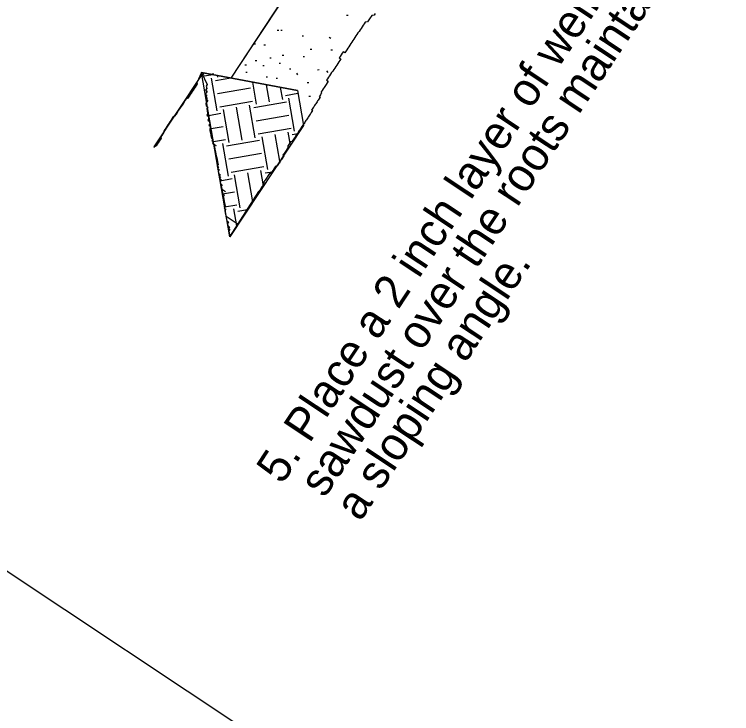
# Model space of a CAD drawing. Extents: x 561231 to 564240, y 590260 to 602519.
# Drawn here: x 563562.9 to 563643.1, y 590442.9 to 590521.1 of the extents above; entities that cross this region are included whole.
import ezdxf

# ---------------------------------------------------------------- set-up
doc = ezdxf.new("R2010")
doc.units = 0
doc.layers.add('Old_Level_1', color=7, linetype='Continuous')

msp = doc.modelspace()

# ---------------------------------------------------------------- linework, layer by layer
at = {"layer": 'Old_Level_1'}
for p, q in [((563587.103, 590513.976), (563592.802, 590522.566)), ((563587.666, 590514.825), (563592.806, 590522.572)), ((563600.035, 590521.027), (563600.201, 590521.028)), ((563592.268, 590519.336), (563592.434, 590519.337)), ((563592.663, 590519.325), (563592.828, 590519.325)), ((563595.062, 590518.691), (563595.227, 590518.692)), ((563598.077, 590518.561), (563598.262, 590518.466)), ((563589.854, 590517.747), (563589.733, 590517.937)), ((563590.783, 590517.705), (563590.949, 590517.706)), ((563595.972, 590517.233), (563596.138, 590517.233)), ((563592.834, 590516.546), (563592.999, 590516.547)), ((563595.161, 590516.412), (563595.326, 590516.413)), ((563598.277, 590517.162), (563598.442, 590517.162)), ((563589.811, 590515.935), (563589.977, 590515.936)), ((563591.439, 590516.265), (563591.604, 590516.265)), ((563592.474, 590515.644), (563592.639, 590515.644)), ((563588.659, 590515.459), (563588.824, 590515.46)), ((563590.649, 590515.379), (563590.815, 590515.38)), ((563593.629, 590515.013), (563593.795, 590515.013)), ((563596.794, 590514.926), (563596.959, 590514.927)), ((563583.836, 590514.387), (563578.46, 590506.281)), ((563583.842, 590514.396), (563578.466, 590506.291)), ((563586.951, 590496.248), (563583.813, 590514.593)), ((563583.813, 590514.593), (563594.535, 590512.583)), ((563594.535, 590512.583), (563583.813, 590514.593)), ((563583.879, 590514.21), (563584.098, 590514.54)), ((563585.064, 590514.359), (563583.888, 590514.156)), ((563585.006, 590514.468), (563585.171, 590514.468)), ((563585.623, 590514.104), (563585.597, 590514.259)), ((563588.744, 590514.631), (563588.909, 590514.631)), ((563591.025, 590514.123), (563591.191, 590514.124)), ((563594.583, 590514.335), (563594.462, 590514.525)), ((563597.954, 590514.604), (563597.833, 590514.794)), ((563585.548, 590510.316), (563584.917, 590513.982)), ((563587.089, 590513.979), (563585.347, 590513.679)), ((563589.948, 590511.074), (563589.527, 590513.522)), ((563591.415, 590511.326), (563591.087, 590513.23)), ((563592.142, 590513.986), (563592.308, 590513.987)), ((563595.634, 590513.482), (563595.799, 590513.483)), ((563589.266, 590512.843), (563585.599, 590512.212)), ((563592.881, 590511.579), (563592.648, 590512.937)), ((563594.535, 590512.583), (563595.192, 590508.671)), ((563594.541, 590512.593), (563595.199, 590508.68)), ((563584.312, 590511.676), (563584.416, 590511.607)), ((563594.591, 590512.251), (563593.184, 590512.009)), ((563594.214, 590508.059), (563593.583, 590511.726)), ((563595.824, 590511.947), (563595.99, 590511.947)), ((563589.518, 590511.377), (563585.852, 590510.746)), ((563589.814, 590507.302), (563589.183, 590510.968)), ((563593.311, 590511.275), (563589.645, 590510.644)), ((563585.978, 590510.012), (563584.637, 590509.781)), ((563586.881, 590506.796), (563586.25, 590510.463)), ((563588.348, 590507.049), (563587.716, 590510.716)), ((563593.564, 590509.809), (563589.897, 590509.177)), ((563586.231, 590508.546), (563584.887, 590508.314)), ((563595.192, 590508.671), (563586.951, 590496.248)), ((563593.816, 590508.342), (563590.15, 590507.711)), ((563592.556, 590504.697), (563592.042, 590507.686)), ((563593.755, 590506.504), (563593.508, 590507.938)), ((563594.578, 590507.744), (563593.938, 590507.634)), ((563586.483, 590507.079), (563585.138, 590506.847)), ((563590.272, 590507.003), (563586.605, 590506.371)), ((563591.206, 590503.766), (563590.575, 590507.432)), ((563585.18, 590506.603), (563585.423, 590506.441)), ((563586.807, 590503.008), (563586.175, 590506.675)), ((563590.524, 590505.536), (563586.858, 590504.905)), ((563590.777, 590504.07), (563587.11, 590503.439)), ((563590.736, 590501.953), (563590.441, 590503.661)), ((563588.14, 590499.489), (563587.509, 590503.156)), ((563589.537, 590500.146), (563588.975, 590503.409)), ((563591.751, 590503.482), (563590.903, 590503.337)), ((563587.237, 590502.705), (563585.887, 590502.473)), ((563586.035, 590501.605), (563586.482, 590501.308)), ((563587.49, 590501.238), (563586.137, 590501.006)), ((563587.742, 590499.772), (563586.388, 590499.539)), ((563587.761, 590497.468), (563587.434, 590499.368)), ((563588.943, 590499.25), (563587.864, 590499.064)), ((563586.558, 590498.545), (563587.889, 590497.662)), ((563586.903, 590496.531), (563587.067, 590496.422))]:
    msp.add_line(p, q, dxfattribs=at)
msp.add_lwpolyline([(563698.589, 591448.685), (563200.53, 590699.06), (563725.267, 590350.419), (564223.327, 591100.044)], close=True, dxfattribs=at)
for points in [[(563603.233, 590521.199), (563603.12, 590521.028), (563602.836, 590520.97), (563602.609, 590520.628), (563602.383, 590520.287), (563602.099, 590520.23), (563601.985, 590520.059), (563601.872, 590519.888), (563601.759, 590519.717), (563601.646, 590519.546), (563601.532, 590519.376), (563601.419, 590519.205), (563601.306, 590519.034), (563601.193, 590518.864), (563601.079, 590518.693), (563600.966, 590518.522), (563600.853, 590518.351), (563600.739, 590518.18), (563600.626, 590518.01), (563600.513, 590517.839), (563600.4, 590517.668), (563600.286, 590517.497), (563600.173, 590517.327), (563600.06, 590517.155), (563599.833, 590516.814), (563599.662, 590516.928), (563599.549, 590516.757), (563599.435, 590516.586), (563599.322, 590516.415), (563599.209, 590516.245), (563599.38, 590516.131), (563599.266, 590515.96), (563599.153, 590515.789), (563599.04, 590515.619), (563598.927, 590515.448), (563598.814, 590515.277), (563598.7, 590515.107), (563598.587, 590514.936), (563598.474, 590514.765), (563598.36, 590514.594), (563598.247, 590514.424), (563598.134, 590514.253), (563598.021, 590514.082), (563597.907, 590513.911), (563597.794, 590513.74), (563597.965, 590513.627), (563597.739, 590513.285), (563597.512, 590512.944), (563597.399, 590512.773), (563597.285, 590512.603), (563597.172, 590512.431), (563597.133, 590512.372)], [(563583.813, 590514.593), (563583.282, 590513.47), (563583.311, 590513.328), (563583.198, 590513.157), (563583.084, 590512.986), (563582.971, 590512.816), (563582.857, 590512.645), (563582.744, 590512.475), (563582.631, 590512.304), (563582.518, 590512.133), (563582.405, 590511.962), (563582.235, 590511.706), (563582.092, 590511.677), (563581.979, 590511.506), (563581.809, 590511.25), (563581.696, 590511.08), (563581.526, 590510.823), (563581.413, 590510.653), (563581.243, 590510.396), (563581.073, 590510.14), (563580.959, 590509.969), (563580.79, 590509.713), (563580.591, 590509.599), (563580.478, 590509.428), (563580.365, 590509.258), (563580.252, 590509.087), (563580.138, 590508.916), (563580.025, 590508.745), (563579.912, 590508.575), (563579.798, 590508.404), (563579.685, 590508.233), (563579.572, 590508.062), (563579.6, 590507.921), (563579.487, 590507.749), (563579.374, 590507.579), (563579.261, 590507.408), (563579.289, 590507.266), (563579.176, 590507.095), (563579.062, 590506.924), (563578.949, 590506.754), (563578.836, 590506.583), (563578.723, 590506.412), (563578.524, 590506.298), (563578.468, 590506.213)], [(563583.813, 590514.593), (563584.433, 590513.258), (563584.32, 590513.088), (563584.378, 590512.804), (563584.265, 590512.633), (563584.436, 590512.52), (563584.322, 590512.349), (563584.209, 590512.178), (563584.38, 590512.065), (563584.266, 590511.894), (563584.437, 590511.781), (563584.324, 590511.61), (563584.495, 590511.496), (563584.382, 590511.326), (563584.268, 590511.155), (563584.326, 590510.871), (563584.497, 590510.758), (563584.384, 590510.587), (563584.441, 590510.303), (563584.499, 590510.019), (563584.385, 590509.848), (563584.557, 590509.735), (563584.614, 590509.45), (563584.501, 590509.28), (563584.672, 590509.166), (563584.729, 590508.882), (563584.616, 590508.711), (563584.787, 590508.598), (563584.731, 590508.143), (563584.789, 590507.859), (563584.846, 590507.575), (563584.904, 590507.291), (563585.075, 590507.178), (563584.961, 590507.007), (563585.133, 590506.894), (563585.019, 590506.723), (563585.19, 590506.61), (563585.248, 590506.325), (563585.305, 590506.041), (563585.363, 590505.757), (563585.42, 590505.473), (563585.478, 590505.189), (563585.535, 590504.905), (563585.593, 590504.621), (563585.651, 590504.336), (563585.538, 590504.166), (563585.708, 590504.052), (563585.595, 590503.881), (563585.766, 590503.768), (563585.652, 590503.597), (563585.71, 590503.313), (563585.881, 590503.2), (563585.768, 590503.029), (563585.939, 590502.916), (563585.826, 590502.745), (563585.997, 590502.632), (563585.883, 590502.461), (563585.941, 590502.177), (563586.112, 590502.064), (563585.998, 590501.893), (563586.056, 590501.609), (563586.113, 590501.325), (563586.171, 590501.04), (563586.342, 590500.927), (563586.228, 590500.756), (563586.286, 590500.472), (563586.344, 590500.188), (563586.402, 590499.904), (563586.459, 590499.62), (563586.345, 590499.449), (563586.516, 590499.336), (563586.403, 590499.165), (563586.461, 590498.881), (563586.519, 590498.597), (563586.576, 590498.313), (563586.634, 590498.028), (563586.804, 590497.915), (563586.691, 590497.745), (563586.749, 590497.46), (563586.92, 590497.347), (563586.807, 590497.176), (563586.977, 590497.063), (563586.864, 590496.892), (563586.951, 590496.248), (563586.951, 590496.248)], [(563597.172, 590512.431), (563597.228, 590512.309), (563597.16, 590512.208), (563597.093, 590512.106), (563597.025, 590512.004), (563596.958, 590511.903), (563597.059, 590511.836), (563596.992, 590511.734), (563596.925, 590511.632), (563596.857, 590511.53), (563596.789, 590511.429), (563596.723, 590511.327), (563596.655, 590511.226), (563596.588, 590511.125), (563596.52, 590511.023), (563596.453, 590510.921), (563596.385, 590510.819), (563596.318, 590510.718), (563596.25, 590510.616), (563596.183, 590510.514), (563596.116, 590510.413), (563596.218, 590510.346), (563596.15, 590510.244), (563596.083, 590510.142), (563596.015, 590510.04), (563595.948, 590509.939), (563595.881, 590509.837), (563595.813, 590509.736), (563595.746, 590509.634), (563595.678, 590509.533), (563595.611, 590509.431), (563595.543, 590509.329), (563595.476, 590509.228), (563595.408, 590509.126), (563595.341, 590509.024), (563595.274, 590508.923), (563595.206, 590508.821), (563595.139, 590508.719), (563595.072, 590508.618), (563595.004, 590508.517), (563594.937, 590508.415), (563594.869, 590508.313), (563594.802, 590508.211), (563594.735, 590508.11), (563594.667, 590508.008), (563594.6, 590507.906), (563594.532, 590507.804), (563594.465, 590507.703), (563594.398, 590507.602), (563594.33, 590507.5), (563594.263, 590507.398), (563594.195, 590507.297), (563594.128, 590507.195), (563594.06, 590507.093), (563593.993, 590506.992), (563593.926, 590506.89), (563593.756, 590506.856), (563593.689, 590506.755), (563593.621, 590506.653), (563593.554, 590506.551), (563593.487, 590506.45), (563593.419, 590506.348), (563593.521, 590506.281), (563593.453, 590506.179), (563593.386, 590506.077), (563593.319, 590505.976), (563593.252, 590505.874), (563593.184, 590505.772), (563593.117, 590505.671), (563593.049, 590505.569), (563592.982, 590505.467), (563592.914, 590505.366), (563593.016, 590505.299), (563592.948, 590505.197), (563592.881, 590505.095), (563592.814, 590504.994), (563592.746, 590504.892), (563592.679, 590504.791), (563592.611, 590504.689), (563592.544, 590504.587), (563592.477, 590504.486), (563592.409, 590504.384), (563592.342, 590504.282), (563592.274, 590504.181), (563592.106, 590504.147), (563592.038, 590504.045), (563591.971, 590503.943), (563591.903, 590503.841), (563591.836, 590503.74), (563591.769, 590503.638), (563591.701, 590503.537), (563591.634, 590503.435), (563591.566, 590503.334), (563591.397, 590503.3), (563591.33, 590503.198), (563591.262, 590503.096), (563591.194, 590502.994), (563591.128, 590502.893), (563591.06, 590502.791), (563590.993, 590502.69), (563590.925, 590502.588)], [(563590.925, 590502.588), (563590.858, 590502.486), (563590.791, 590502.385), (563590.723, 590502.283), (563590.757, 590502.114), (563590.69, 590502.013), (563590.623, 590501.911), (563590.555, 590501.809), (563590.488, 590501.707), (563590.42, 590501.606), (563590.353, 590501.504), (563590.286, 590501.403), (563590.218, 590501.301), (563586.951, 590496.248), (563586.951, 590496.248), (563590.218, 590501.301)]]:
    msp.add_lwpolyline(points, dxfattribs=at)

# ---------------------------------------------------------------- texts
for s, p in [(' the root collar is at ground level.', (563526.807, 590512.221)), ('5. Place a 2 inch layer of well rotted ', (563592.813, 590468.438)), (' sawdust over the roots maintaining ', (563596.799, 590465.794)), (' a sloping angle.', (563600.785, 590463.149))]:
    msp.add_text(s, height=3.72047, rotation=56.44242, dxfattribs=at).set_placement(p)

doc.saveas('drawing.dxf')
